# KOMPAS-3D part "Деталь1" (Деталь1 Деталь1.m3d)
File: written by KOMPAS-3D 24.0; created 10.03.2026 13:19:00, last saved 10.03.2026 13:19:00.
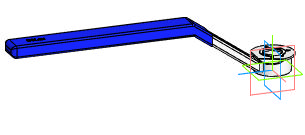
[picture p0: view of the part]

Document properties: Автор: R2D2; Полное имя файла: E:\Работа\Зайцев\BV3232P(4pc)-FP-3WL-F-ISO-H Кран шаровой DN.ru Ду15-100 Ру16\DN100\исходные материалы\Деталь1 Деталь1.m3d

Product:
- Body: Твердое тело1  | qty 1
- Part/product: Деталь1
    additional columns: Типовые

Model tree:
1. Твердое тело1  (labels: Твердое тело1)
